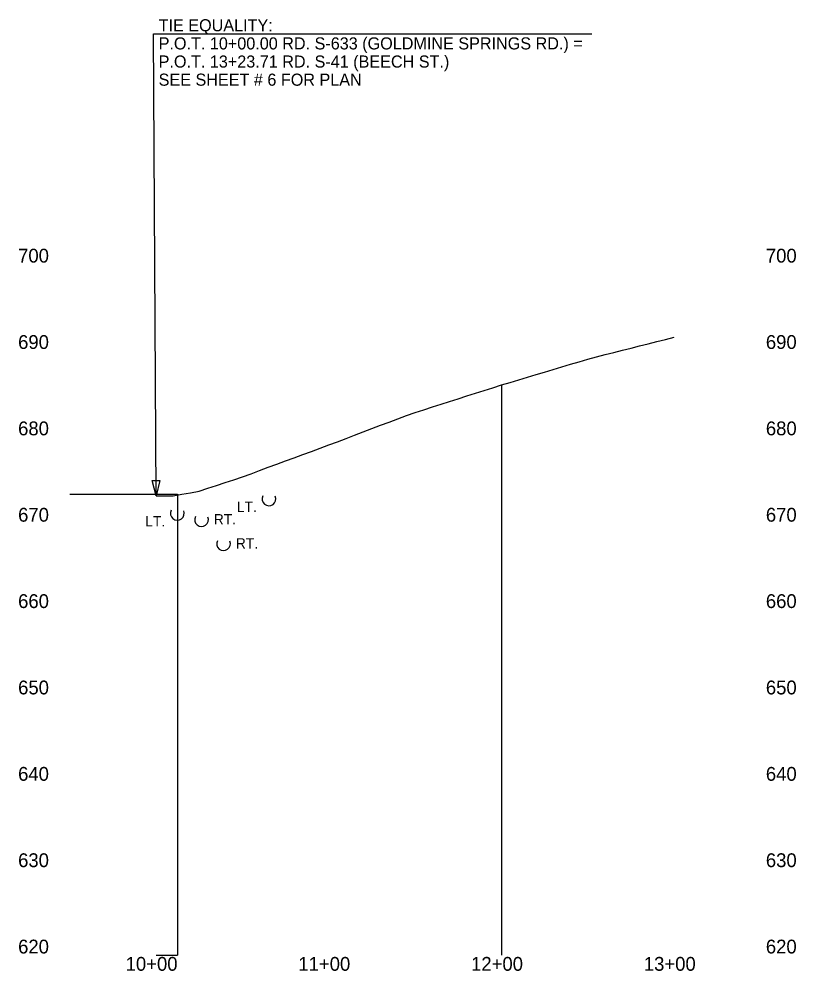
# Model space of a CAD drawing. Extents: x 16383870 to 16385930, y 46196762 to 46198956.
# Drawn here: x 16384272 to 16384722, y 46196762 to 46197313 of the extents above; entities that cross this region are included whole.
import ezdxf

# ---------------------------------------------------------------- set-up
doc = ezdxf.new("R2010")
doc.units = 0
for name, color, linetype in [('Default', 7, 'Continuous'), ('RD_DDB_ElevTX', 7, 'Continuous'), ('RD_DDB_Profile_EX', 7, 'Continuous'), ('RD_DDB_StaTX', 7, 'Continuous'), ('RD_SHT_MjGrid', 7, 'Continuous'), ('RD_SHT_MnGrid', 7, 'Continuous'), ('RD_TX_Misc1', 7, 'Continuous')]:
    doc.layers.add(name, color=color, linetype=linetype)

msp = doc.modelspace()

# ---------------------------------------------------------------- linework, layer by layer
at = {"layer": 'Default'}
for centre in [(16384416.72, 46197035.01), (16384363.69, 46197026.63), (16384377.69, 46197022.98), (16384390.44, 46197009.03)]:
    msp.add_arc(centre, 3.98, 153.828, 22.5332, dxfattribs=at)
at = {"layer": 'RD_DDB_Profile_EX'}
msp.add_lwpolyline([(16384351.35, 46197036.69), (16384356.35, 46197036.73), (16384361.35, 46197036.83), (16384366.35, 46197037.65), (16384371.35, 46197038.48), (16384376.35, 46197039.54), (16384381.35, 46197041.17), (16384386.35, 46197042.81), (16384391.35, 46197044.45), (16384396.35, 46197046.09), (16384401.35, 46197047.74), (16384406.35, 46197049.59), (16384411.35, 46197051.44), (16384416.35, 46197053.29), (16384421.35, 46197055.14), (16384426.35, 46197056.99), (16384431.35, 46197058.84), (16384436.35, 46197060.69), (16384441.35, 46197062.52), (16384446.35, 46197064.36), (16384451.35, 46197066.21), (16384456.35, 46197068.1), (16384461.35, 46197070.02), (16384466.35, 46197071.93), (16384471.35, 46197073.83), (16384476.35, 46197075.71), (16384481.35, 46197077.59), (16384486.35, 46197079.47), (16384491.35, 46197081.35), (16384496.35, 46197083.23), (16384501.35, 46197085.04), (16384506.35, 46197086.62), (16384511.35, 46197088.2), (16384516.35, 46197089.79), (16384521.35, 46197091.37), (16384526.35, 46197092.99), (16384531.35, 46197094.57), (16384536.35, 46197096.16), (16384541.35, 46197097.74), (16384546.35, 46197099.32), (16384551.35, 46197100.94), (16384556.35, 46197102.45), (16384561.35, 46197103.95), (16384566.35, 46197105.45), (16384571.35, 46197106.94), (16384576.35, 46197108.44), (16384581.35, 46197109.94), (16384586.35, 46197111.43), (16384591.35, 46197112.93), (16384596.35, 46197114.43), (16384601.35, 46197115.93), (16384606.35, 46197117.31), (16384611.35, 46197118.57), (16384616.35, 46197119.83), (16384621.35, 46197121.09), (16384626.35, 46197122.34), (16384631.35, 46197123.6), (16384636.35, 46197124.85), (16384641.35, 46197126.11), (16384646.35, 46197127.36), (16384651.35, 46197128.62)], dxfattribs=at)
at = {"layer": 'RD_SHT_MjGrid'}
for p, q in [((16384349.81, 46197304.27), (16384603.74, 46197304.27)), ((16384351.35, 46197036.69), (16384349.81, 46197304.27))]:
    msp.add_line(p, q, dxfattribs=at)
at = {"layer": 'RD_SHT_MnGrid'}
msp.add_lwpolyline([(16384353.55, 46197045.71), (16384351.35, 46197036.69), (16384349.05, 46197045.68)], close=True, dxfattribs=at)
at = {"layer": 'RD_TX_Misc1'}
for p, q in [((16384551.35, 46197100.94), (16384551.35, 46196770.8)), ((16384301.4, 46197037.78), (16384363.78, 46197037.78)), ((16384363.78, 46197037.78), (16384363.78, 46196770.8)), ((16384351.35, 46196770.8), (16384363.78, 46196770.8))]:
    msp.add_line(p, q, dxfattribs=at)

# ---------------------------------------------------------------- texts
at = {"layer": 'Default'}
for s, p in [('LT.', (16384398.13, 46197027.39)), ('LT.', (16384345.1, 46197019.01)), ('RT.', (16384384.77, 46197020.2)), ('RT.', (16384397.52, 46197006.25))]:
    msp.add_text(s, height=6, dxfattribs=at).set_placement(p)
at = {"layer": 'RD_DDB_ElevTX'}
for s, p in [('700', (16384271.5, 46197171.8)), ('700', (16384704.41, 46197171.8)), ('690', (16384271.5, 46197121.8)), ('690', (16384704.41, 46197121.8)), ('680', (16384271.5, 46197071.8)), ('680', (16384704.41, 46197071.8)), ('670', (16384271.5, 46197021.8)), ('670', (16384704.41, 46197021.8)), ('660', (16384271.5, 46196971.8)), ('660', (16384704.41, 46196971.8)), ('650', (16384271.5, 46196921.8)), ('650', (16384704.41, 46196921.8)), ('640', (16384271.5, 46196871.8)), ('640', (16384704.41, 46196871.8)), ('630', (16384271.5, 46196821.8)), ('630', (16384704.41, 46196821.8)), ('620', (16384271.5, 46196771.8)), ('620', (16384704.41, 46196771.8))]:
    msp.add_text(s, height=8, dxfattribs=at).set_placement(p)
at = {"layer": 'RD_DDB_StaTX'}
for s, p in [('10+00', (16384333.76, 46196761.8)), ('11+00', (16384433.76, 46196761.8)), ('12+00', (16384533.76, 46196761.8)), ('13+00', (16384633.76, 46196761.8))]:
    msp.add_text(s, height=8, dxfattribs=at).set_placement(p)
at = {"layer": 'RD_SHT_MjGrid'}
for s, p in [('TIE EQUALITY:', (16384352.87, 46197305.7)), ('P.O.T. 10+00.00 RD. S-633 (GOLDMINE SPRINGS RD.) =', (16384352.87, 46197295.2)), ('P.O.T. 13+23.71 RD. S-41 (BEECH ST.)', (16384352.87, 46197284.7)), ('SEE SHEET # 6 FOR PLAN', (16384352.87, 46197274.2))]:
    msp.add_text(s, height=7, dxfattribs=at).set_placement(p)

doc.saveas('drawing.dxf')
